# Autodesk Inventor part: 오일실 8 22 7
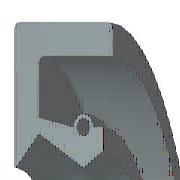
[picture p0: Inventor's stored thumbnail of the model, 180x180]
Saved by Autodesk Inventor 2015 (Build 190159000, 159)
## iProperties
IsCustomPart: 1
Created: 2012-02
Part Number: 오일실 8 22 7
Material: 고무
Description: 오일-실
Document SubType Name: Modeling
Standard: KS B 2804
Designer: mduedu
Standards Organization: KS
Language: ko-KR
Size Designation: D - 8 22 7
Categories: <MemberInstance><Categories><Category DisplayName="샤프트 부품" InternalName="7f7aeb1f-a693-4053-b835-cee3144e0d98" Mnemonic="SHFT"><Category DisplayName="실링" Intern
Density: 0.93 g/cm^3
Appearance: Rubber - Black - Version 1.1
Mass: 1.28441 g
Surface Area: 18.2787 cm^2
Volume: 1.38108 cm^3
Author: mduedu
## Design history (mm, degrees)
revolve "본체" stored, may be unused: angle "d17" = 90 deg
revolve "스프링1" stored, may be unused: angle "d18" = 90 deg
body "Solid1"
sketch "스케치1"
  geometry: L1 (0, 11)-(7, 11); L2 (7, 9.25)-(1.75, 9.25); L3 (1.75, 5.75)-(4.9, 4); L4 (4.9, 4)-(0, 4); L5 (0, 0)-(9.586, 0) reference; L6 (4.9, 4)-(6.3, 4.875); L7 (0, 18)-(0, -3) reference; L8 (-1.941, 0)-(11.507, 0) reference; L9 (4.2, 6.1)-(1.75, 6.59); L10 (1.75, 6.59)-(1.75, 9.25); L11 (0, 11)-(0, 4.088); L12 (4.9, 4)-(0, 4); L13 (1.75, 5.75)-(0.152, 4.028); L14 (7, 11)-(7, 9.25); L15 (5.6, 6.1)-(6.3, 6.1); L16 (6.3, 6.1)-(6.3, 4.875); C1 r 0.455 at (4.9, 6.1); A1 r 0.7 centre (4.9, 6.1) between (5.6, 6.1) and (4.2, 6.1); A2 r 0.088 centre (0.088, 4.088) between (0, 4.088) and (0.152, 4.028); 1 further point
  constraints: 28 end point, 5 horizontal alignment, 5 point on line, 4 point on circle, 4 vertical alignment, 3 centre point, 3 tangent, 2 collinear, 2 horizontal, 2 perpendicular, 1 coincident, 1 parallel
  dimensions: "d0" = 22 diameter of L1 L5 (= SD2); "d1" = 1.75 distance of L1.end L2.start (= SD); "d2" = 0.91 diameter of C1 (= SPDI); "d3" = 1.4 diameter of A1 (= SPDA); "d4" = 8 diameter of L3.end L5 (= NND); "d5" = 11.5 diameter of L3.start L5 (= TKDM); "d7" = 13.18 diameter of L9.end L5 (= TKDM + 0.24 x SWDT); "d8" = 1.75 distance between parallel lines of L11 L10 (= SD); "d9" = 4.9 distance from line of L11 C1.centre (= SPDST); "d10" = 12.2 diameter of C1.centre L5 (= HLDM); "d11" = 0.0875 radius of A2 (= 0.25 x LAB); "d12" = 6.3 distance between parallel lines of L11 L16 (= SDI); "d13" = 9.75 diameter of L6.end L5 (= ABDM); "d14" = 7 distance from line of L11 L1.end (= SWDT)
fillet "모깎기1" dims "d6" = 0.3 (= RR)
other parameters: "SD2" = 22 [user parameter; used in 1 equation term], "SWDT" = 7 [user parameter; used in 2 equation terms], "RR" = 0.3 [user parameter; used in 1 equation term], "SD" = 1.75 [user parameter; used in 2 equation terms], "NND" = 8 [user parameter; used in 1 equation term], "SPDA" = 1.4 [user parameter; used in 1 equation term], "SPDI" = 0.91 [user parameter; used in 1 equation term], "TKDM" = 11.5 [user parameter; used in 2 equation terms], "HLDM" = 12.2 [user parameter; used in 1 equation term], "ABDM" = 9.75 [user parameter; used in 1 equation term], "SDI" = 6.3 [user parameter; used in 1 equation term], "SPDST" = 4.9 [user parameter; used in 1 equation term], "LAB" = 0.35 [user parameter; used in 1 equation term], "d15" = 0, "d16" = 0, "d19" = 0
